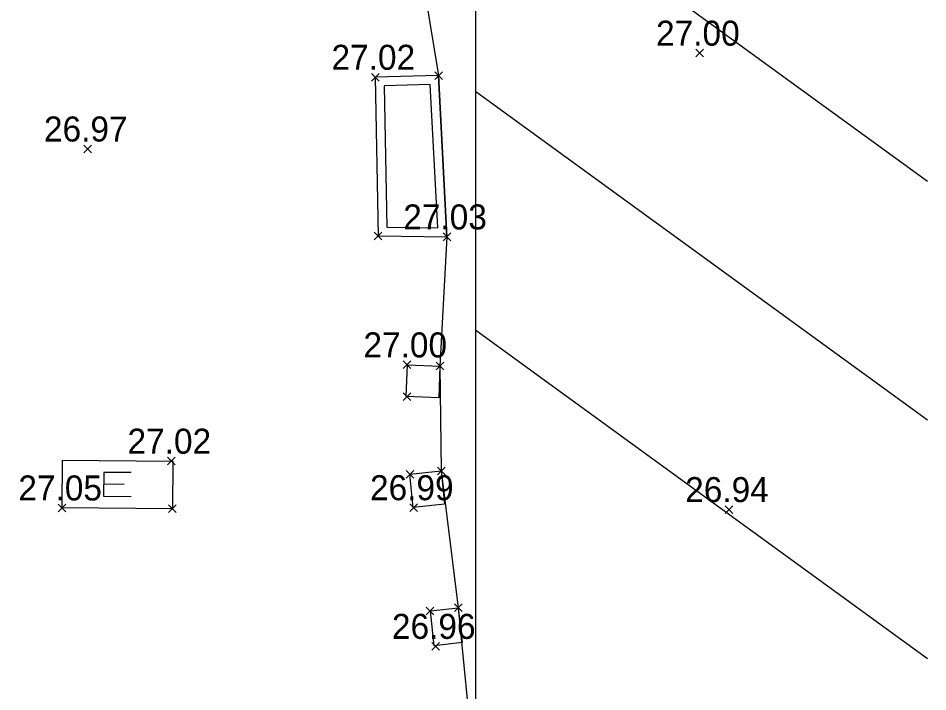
# Model space of a CAD drawing. Extents: x 37864 to 38032, y 453991 to 454052.
# Drawn here: x 37877.77 to 37888.14, y 454008.41 to 454016.08 of the extents above; entities that cross this region are included whole.
import ezdxf

# ---------------------------------------------------------------- set-up
doc = ezdxf.new("R2010")
doc.units = 0
for name, color, linetype in [('DH_CALCUL SURFACE-TEXTE', 7, 'Continuous'), ('GO_POTEAU', 7, 'Continuous'), ('PS_Bolt', 7, 'Continuous'), ('PS_Dim', 7, 'Continuous'), ('PS_Hidden', 7, 'Continuous'), ('PS_Object', 7, 'Continuous'), ('PS_Pos', 7, 'Continuous'), ('PS_Weld', 7, 'Continuous'), ('SO_SANITAIRE DETAILLE', 7, 'Continuous')]:
    doc.layers.add(name, color=color, linetype=linetype)

# ---------------------------------------------------------------- blocks, each defined once
blk = doc.blocks.new('V-TAMPON')
for p, q in [((0, 0), (0, 1)), ((0, 1), (1, 1)), ((1, 1), (1, 0)), ((0.375, 0.75), (0.375, 0.25)), ((0.625, 0.75), (0.375, 0.75)), ((0.5625, 0.5), (0.375, 0.5)), ((0.375, 0.25), (0.625, 0.25)), ((1, 0), (0, 0))]:
    blk.add_line(p, q)
blk = doc.blocks.new('POTO_REC')
at = {"layer": 'PS_Weld'}
for p, q in [((0, 1), (1, 1)), ((0, 0), (0, 1)), ((1, 1), (1, 0)), ((1, 0), (0, 0))]:
    blk.add_line(p, q, dxfattribs=at)
blk = doc.blocks.new('POINT_DISPLAY')
for p, q in [((-0.04375, -0.04375), (0.04375, 0.04375)), ((-0.04375, 0.04375), (0.04375, -0.04375))]:
    blk.add_line(p, q)
blk = doc.blocks.new('POINTCOT')
blk.add_blockref('POINT_DISPLAY', (0, 0))

msp = doc.modelspace()

# ---------------------------------------------------------------- linework, layer by layer
at = {"layer": 'PS_Bolt'}
for points in [[(37882.561, 454015.43), (37881.838, 454015.412), (37881.872, 454013.604), (37882.656, 454013.593), (37882.561, 454015.43)], [(37882.466, 454015.328), (37881.94, 454015.315), (37881.97, 454013.702), (37882.551, 454013.694), (37882.466, 454015.328)]]:
    msp.add_lwpolyline(points, dxfattribs=at)
at = {"layer": 'PS_Dim'}
msp.add_line((37882.985, 454004.477), (37882.985, 454030.398), dxfattribs=at)
at = {"layer": 'PS_Hidden'}
for p, q in [((37888.135, 454014.223), (37882.985, 454017.965)), ((37888.135, 454011.503), (37882.985, 454015.245)), ((37888.135, 454008.784), (37882.985, 454012.526))]:
    msp.add_line(p, q, dxfattribs=at)
at = {"layer": 'PS_Object'}
msp.add_lwpolyline([(37895.242, 454005.264), (37889.943, 454005.178), (37889.917, 454004.706), (37883.591, 454004.486), (37882.985, 454004.477), (37882.985, 454030.398)], dxfattribs=at)
at = {"layer": 'SO_SANITAIRE DETAILLE'}
msp.add_line((37882.985, 454004.477), (37882.985, 454030.285), dxfattribs=at)
msp.add_lwpolyline([(37877.767, 454040.919), (37880.278, 454037.408), (37879.922, 454031.271), (37881.601, 454024.153), (37881.601, 454024.153), (37881.601, 454024.153), (37881.675, 454023.821), (37881.781, 454022.267), (37881.901, 454020.769), (37881.927, 454020.39), (37882.008, 454019.105), (37882.114, 454018.134), (37882.561, 454015.43), (37882.656, 454013.593), (37882.577, 454012.12), (37882.592, 454010.925), (37882.785, 454009.367), (37882.96, 454007.587), (37882.985, 454004.477)], dxfattribs=at)

# ---------------------------------------------------------------- block references
at = {"layer": 'DH_CALCUL SURFACE-TEXTE', "rotation": 2.2526485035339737e-05}
for p in [(37885.539, 454015.687), (37881.838, 454015.412), (37882.561, 454015.43), (37878.559, 454014.595), (37881.872, 454013.604), (37882.656, 454013.593), (37882.202, 454012.135), (37882.577, 454012.12), (37882.2, 454011.771), (37879.512, 454011.039), (37882.592, 454010.925), (37882.235, 454010.888), (37878.267, 454010.505), (37879.526, 454010.496), (37882.277, 454010.508), (37885.871, 454010.486), (37882.785, 454009.367), (37882.465, 454009.33), (37882.527, 454008.928)]:
    msp.add_blockref('POINTCOT', p, dxfattribs=at)
at = {"layer": 'PS_Bolt'}
for p, xscale, yscale, rotation in [((37882.577, 454012.12), 0.36999999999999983, 0.36, 177.66185220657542), ((37882.592, 454010.925), 0.3600000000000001, 0.38, -174.2103553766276), ((37882.785, 454009.367), 0.32000000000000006, 0.4, -173.53318915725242)]:
    msp.add_blockref('POTO_REC', p, dxfattribs=dict(at, xscale=xscale, yscale=yscale, rotation=rotation))
at = {"layer": 'PS_Pos', "xscale": 1.2593298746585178, "yscale": 0.5429269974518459, "rotation": -0.4332564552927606}
msp.add_blockref('V-TAMPON', (37878.267, 454010.505), dxfattribs=at)

# ---------------------------------------------------------------- texts
at = {"layer": 'GO_POTEAU'}
for s, p in [('27.00', (37885.041, 454015.771)), ('27.02', (37881.34, 454015.496)), ('26.97', (37878.061, 454014.679)), ('27.03', (37882.158, 454013.677)), ('27.00', (37881.704, 454012.219)), ('27.02', (37879.014, 454011.122)), ('27.05', (37877.769, 454010.589)), ('26.99', (37881.779, 454010.592)), ('26.94', (37885.373, 454010.57)), ('26.96', (37882.029, 454009.012))]:
    msp.add_text(s, height=0.285, rotation=0, dxfattribs=at).set_placement(p)

doc.saveas('drawing.dxf')
